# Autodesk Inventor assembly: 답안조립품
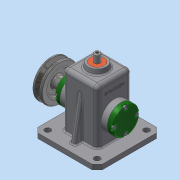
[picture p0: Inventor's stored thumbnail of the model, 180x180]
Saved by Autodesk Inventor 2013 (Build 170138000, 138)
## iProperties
Created: 2016-02
Part Number: 답안조립품
Document SubType Name: Assembly
Designer: Administrator
Author: Administrator
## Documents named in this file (15)
- C:\Users\Administrator\Desktop\460212V1016\답안조립품.iam
- C:\Users\Administrator\Desktop\460212V1016\본체.ipt
- C:\Users\Administrator\Desktop\460212V1016\부시.ipt
- C:\Users\Administrator\Desktop\460212V1016\뒤커버.ipt
- C:\Users\Administrator\Desktop\460212V1016\베어링 12 x 32 x 10.ipt
- C:\Users\Administrator\Desktop\460212V1016\편심축.ipt
- C:\Users\Administrator\Desktop\460212V1016\앞커버.ipt
- C:\Users\Administrator\Desktop\460212V1016\오일실 12 25 7.ipt
- C:\Users\Administrator\Desktop\460212V1016\키 4 x 4 x 10.ipt
- C:\Users\Administrator\Desktop\460212V1016\V벨트풀리.ipt
- C:\Users\Administrator\Desktop\460212V1016\슬라이드.ipt
- C:\Users\Administrator\Desktop\460212V1016\링크.ipt
- C:\Users\Administrator\Desktop\460212V1016\핀 5 x 18.ipt
- C:\Users\Administrator\Desktop\460212V1016\고정핀 1.2 x 10.ipt
- C:\Users\Administrator\Desktop\460212V1016\볼트 M4 x 12.ipt
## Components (11 placed, 4 different names)
1. V벨트풀리:1
2. 핀 5 x 18:1
3. 고정핀 1.2 x 10:1
4. ISO 4762 M4 x 12:1
5. ISO 4762 M4 x 12:3
6. ISO 4762 M4 x 12:4
7. ISO 4762 M4 x 12:5
8. ISO 4762 M4 x 12:2
9. ISO 4762 M4 x 12:6
10. ISO 4762 M4 x 12:7
11. ISO 4762 M4 x 12:8
